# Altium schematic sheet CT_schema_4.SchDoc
size 309 x 321 mm
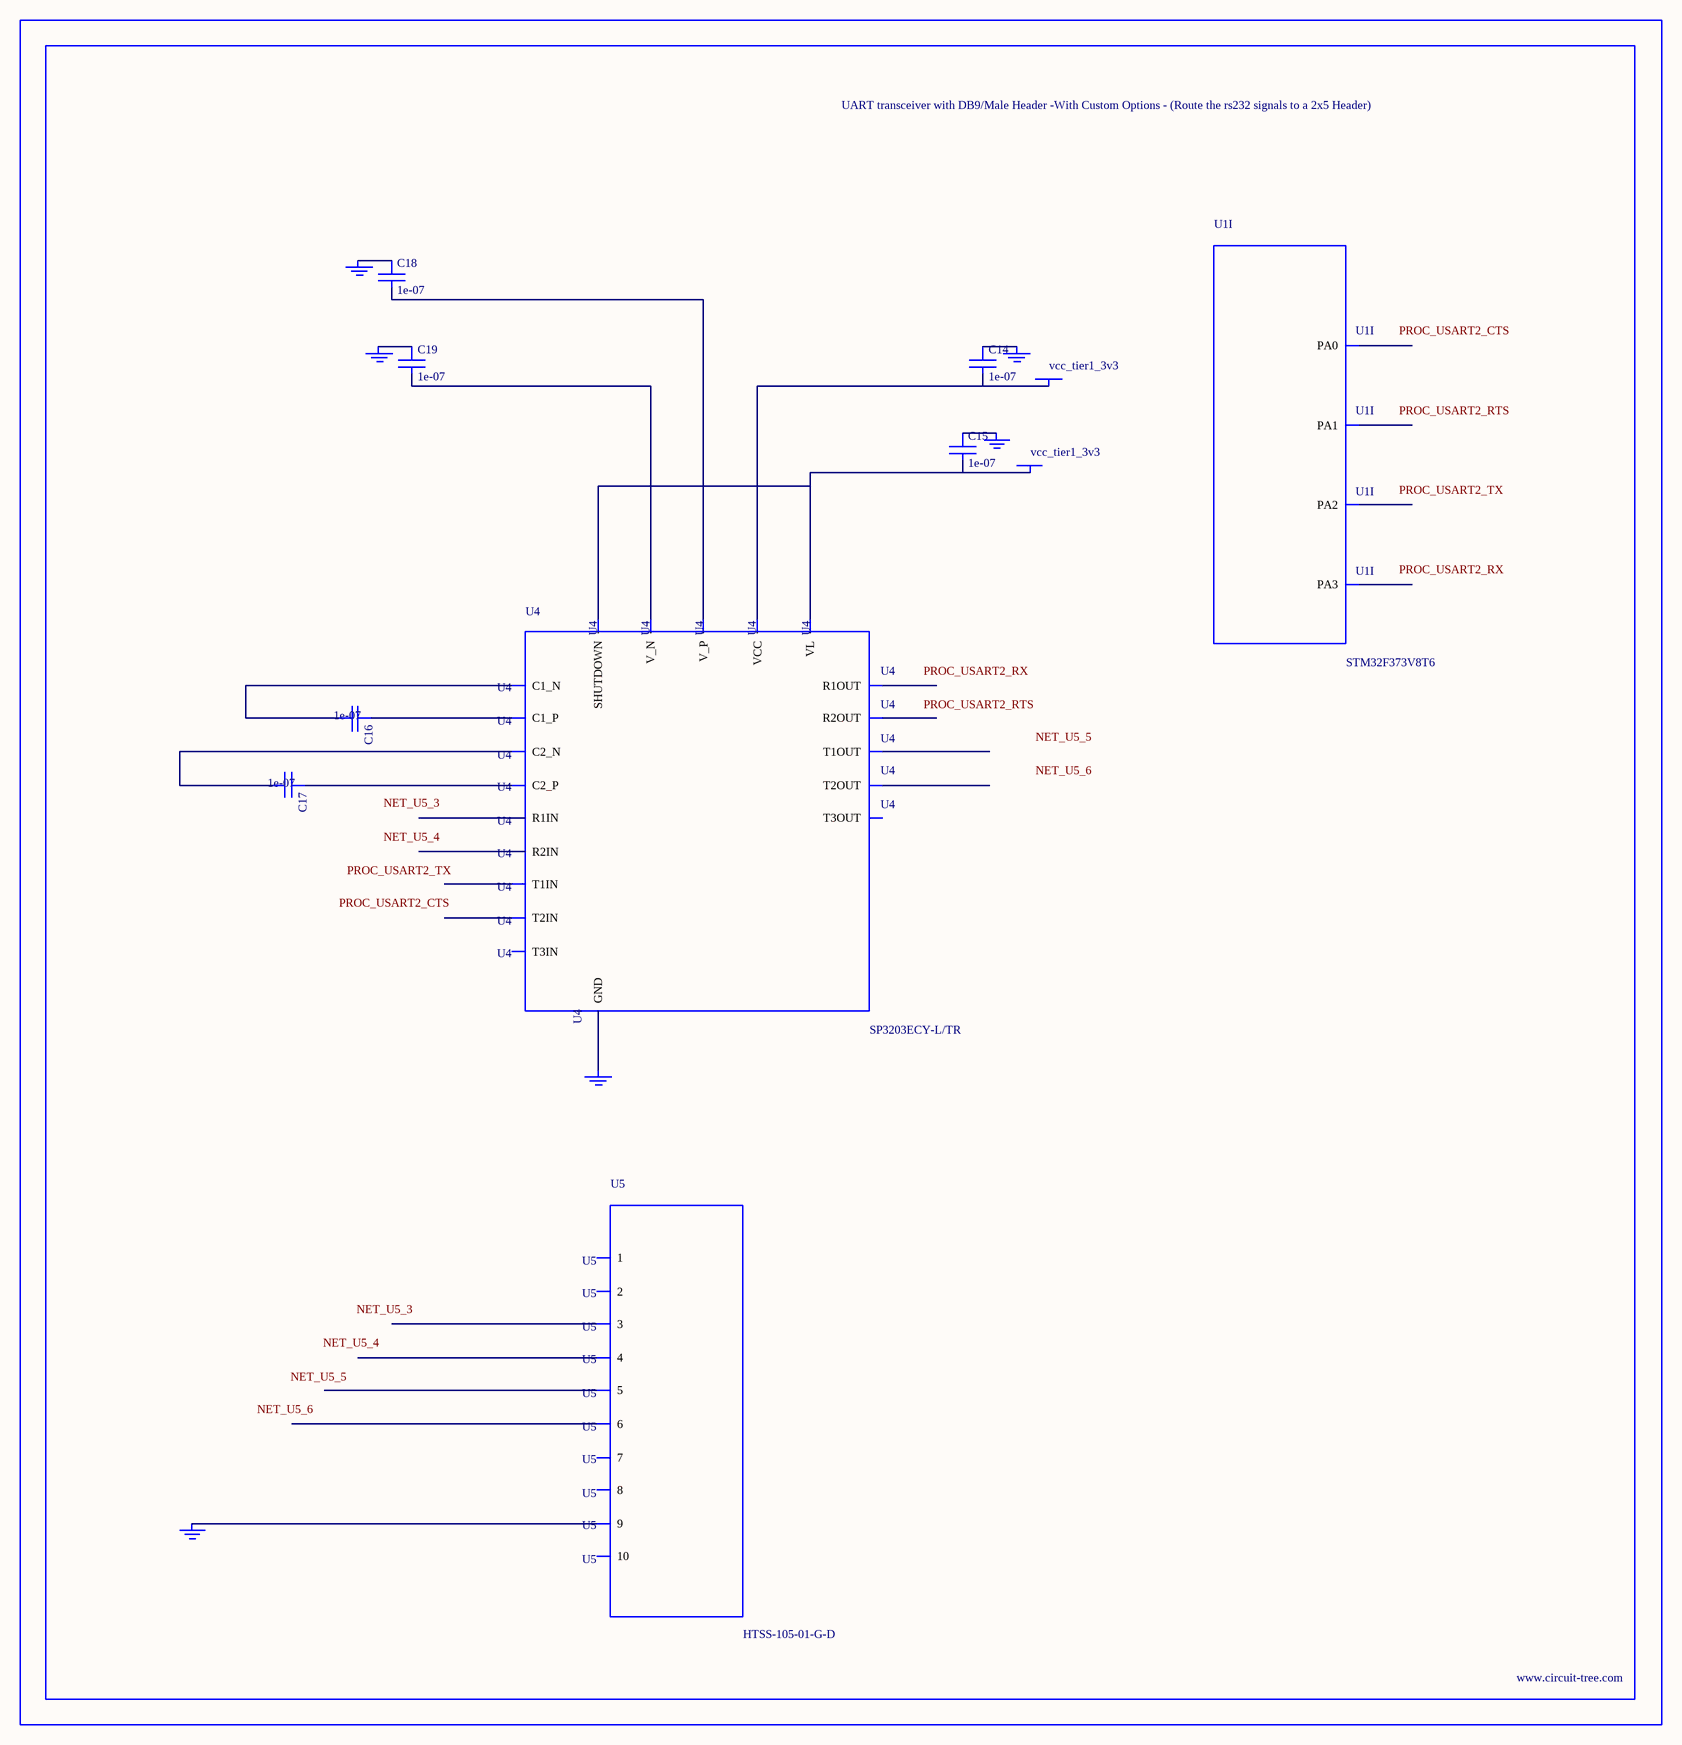
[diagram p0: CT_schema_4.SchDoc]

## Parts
BORDER3  (no value)
C14  1e-07  [C0402]
C15  1e-07  [C0402]
C16  1e-07  [C0402]
C17  1e-07  [C0402]
C18  1e-07  [C0402]
C19  1e-07  [C0402]
GND_INSTANCE_3_0  (no value)
GND_INSTANCE_3_1  (no value)
GND_INSTANCE_3_2  (no value)
GND_INSTANCE_3_3  (no value)
GND_INSTANCE_3_4  (no value)
GND_INSTANCE_3_5  (no value)
POWER_INSTANCE_3_0  vcc_tier1_3v3
POWER_INSTANCE_3_1  vcc_tier1_3v3
U1  STM32F373V8T6  [LQFP100]  (part I of 10)
U4  SP3203ECY-L/TR  [TSSOP20-I]
U5  HTSS-105-01-G-D  [HTSS-105-01-G-D]

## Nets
NetC14_1: C14.1 GND_INSTANCE_3_3.0(GND)
NetC14_2: C14.2 POWER_INSTANCE_3_1.0(PWR) U4.19(VCC)
NetC15_1: C15.1 GND_INSTANCE_3_2.0(GND)
NetC15_2: C15.2 POWER_INSTANCE_3_0.0(PWR) U4.12(VL) U4.20(SHUTDOWN)
NetC16_1: C16.1 U4.1(C1_P)
NetC16_2: C16.2 U4.3(C1_N)
NetC17_1: C17.1 U4.4(C2_P)
NetC17_2: C17.2 U4.5(C2_N)
NetC18_1: C18.1 GND_INSTANCE_3_0.0(GND)
NetC18_2: C18.2 U4.2(V_P)
NetC19_1: C19.1 GND_INSTANCE_3_1.0(GND)
NetC19_2: C19.2 U4.6(V_N)
NetGND_INSTANCE_3_4_0: GND_INSTANCE_3_4.0(GND) U4.18(GND)
NetGND_INSTANCE_3_5_0: GND_INSTANCE_3_5.0(GND) U5.9

Not connected (* = marked no-connect by the designer): U1 23(PA0) 24(PA1) 25(PA2) 26(PA3); U4 7(T1IN) 8(T2IN) 9(T3IN) 10(R2OUT) 11(R1OUT) 13(R2IN) 14(R1IN) 15(T3OUT) 16(T2OUT) 17(T1OUT); U5 1 2 3 4 5 6 7 8 10

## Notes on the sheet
- Labels drawn without touching a wire or pin: NET_U5_3, NET_U5_4, NET_U5_5, NET_U5_6, PROC_USART2_CTS, PROC_USART2_RTS, PROC_USART2_RX, PROC_USART2_TX

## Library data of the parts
BORDER3 = BORDER_PAGE3
C14-C19 = C0402C104K3RACTU
GND_INSTANCE_3_0-GND_INSTANCE_3_5 = GND
POWER_INSTANCE_3_0 POWER_INSTANCE_3_1 = PWR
